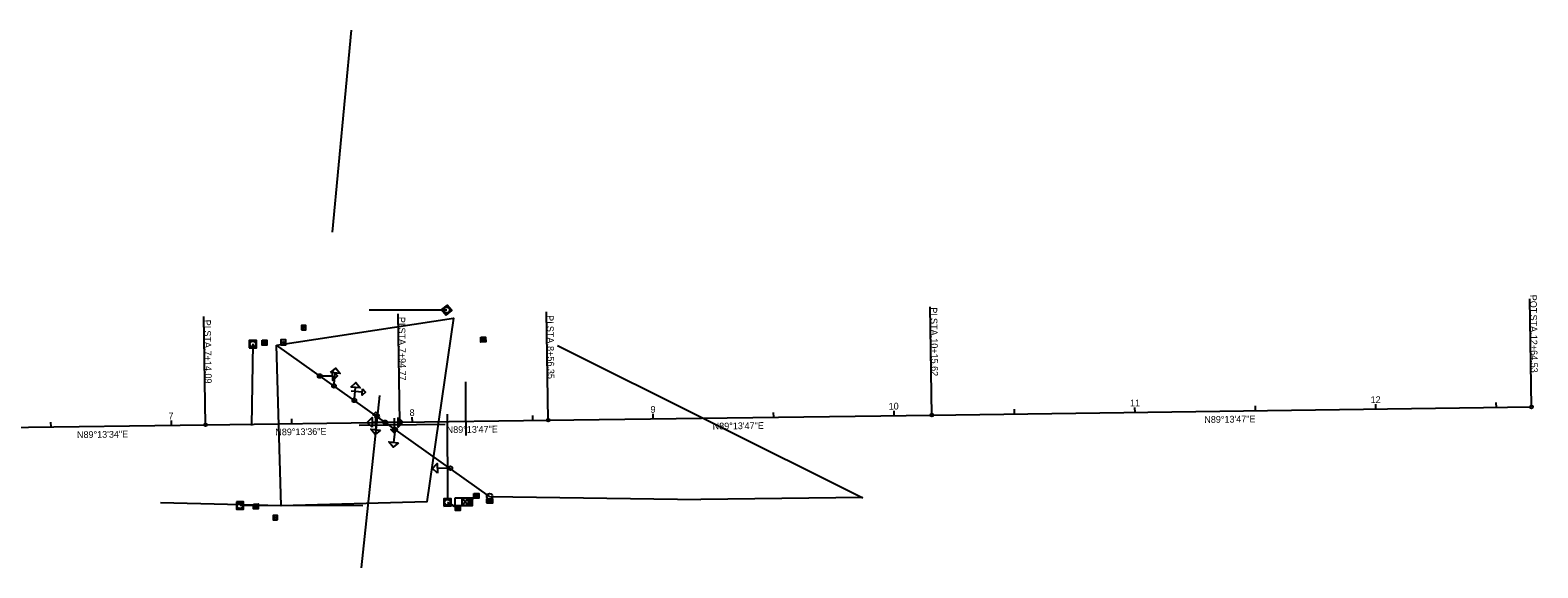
# Model space of a CAD drawing. Extents: x 1369241 to 1370511, y 405823 to 406278.
# Drawn here: x 1369885 to 1370511, y 405850 to 406073 of the extents above; entities that cross this region are included whole.
import ezdxf

# ---------------------------------------------------------------- set-up
doc = ezdxf.new("R2010")
doc.units = 0
for name, color, linetype in [('_CIVIL_CONSTRUCTION', 7, 'Continuous'), ('CM_Corridor_Conceptual', 7, 'Continuous'), ('GE_P_Alignment', 7, 'Continuous'), ('MD_P_ACB_B', 7, 'Continuous'), ('MD_P_ACIC_B', 7, 'Continuous'), ('MD_P_CSS_B', 7, 'Continuous'), ('MD_P_CURB_FACE_BOT', 7, 'Continuous'), ('MD_P_CURB_FACE_TOP', 7, 'Continuous'), ('PF_X_Ground_Line', 7, 'Continuous'), ('PM_P_Crosswalk', 7, 'Continuous'), ('PV_P_Curb', 7, 'Continuous'), ('SC_Scratch1', 7, 'Continuous')]:
    doc.layers.add(name, color=color, linetype=linetype)

msp = doc.modelspace()

# ---------------------------------------------------------------- linework, layer by layer
at = {"layer": '_CIVIL_CONSTRUCTION'}
for p, q in [((1370064.71, 405879.01), (1370067.4, 405876.02)), ((1370067.38, 405879.02), (1370064.73, 405876.01)), ((1370067.38, 405878.33), (1370068.64, 405876.72)), ((1370068.63, 405878.34), (1370067.39, 405876.71)), ((1370074.93, 405878.57), (1370077.43, 405877.07)), ((1370074.93, 405877.07), (1370077.43, 405878.57))]:
    msp.add_line(p, q, dxfattribs=at)
for points in [[(1370061.71, 405878.99), (1370061.73, 405875.99), (1370069.11, 405876.03), (1370069.09, 405879.03)], [(1370061.71, 405878.99), (1370061.73, 405875.99), (1370064.73, 405876.01), (1370064.71, 405879.01)], [(1370064.71, 405879.01), (1370067.38, 405879.02), (1370067.4, 405876.02), (1370064.73, 405876.01)], [(1370067.38, 405878.33), (1370068.63, 405878.34), (1370068.64, 405876.72), (1370067.39, 405876.71)]]:
    msp.add_lwpolyline(points, close=True, dxfattribs=at)
msp.add_lwpolyline([(1370074.93, 405877.07), (1370077.43, 405877.07), (1370077.43, 405878.57), (1370074.93, 405878.57), (1370074.93, 405877.07)], dxfattribs=at)
at = {"layer": 'CM_Corridor_Conceptual'}
for p, q in [((1370006.43, 405929.81), (1370011.03, 405929.86)), ((1370011.63, 405926.51), (1370012.09, 405931.09)), ((1370018.64, 405923.59), (1370023.32, 405923.18)), ((1370020.09, 405920.47), (1370020.49, 405925.05)), ((1370031.96, 405910.55), (1370027.36, 405910.5)), ((1370029.38, 405912.1), (1370028.83, 405907.53)), ((1370028.99, 405908.8), (1370028.94, 405913.5)), ((1370033.56, 405910.56), (1370038.16, 405910.56)), ((1370036.55, 405912.28), (1370036.55, 405907.58)), ((1370036.86, 405906.79), (1370036.31, 405902.22)), ((1370059.06, 405891.48), (1370054.46, 405891.43))]:
    msp.add_line(p, q, dxfattribs=at)
for points in [[(1370010.1, 405931.28), (1370012.29, 405933.08), (1370014.08, 405930.89)], [(1370011.01, 405931.86), (1370013.03, 405929.88), (1370011.05, 405927.86)], [(1370018.49, 405925.21), (1370020.65, 405927.03), (1370022.47, 405924.87)], [(1370023.42, 405924.49), (1370024.64, 405923.05), (1370023.2, 405921.83)], [(1370027.63, 405913.48), (1370028.95, 405914.83), (1370030.3, 405913.51)], [(1370027.39, 405908.5), (1370025.37, 405910.48), (1370027.35, 405912.5)], [(1370030.82, 405907.3), (1370028.59, 405905.55), (1370026.85, 405907.77)], [(1370038.15, 405912.57), (1370040.15, 405910.57), (1370038.15, 405908.57)], [(1370038.3, 405901.99), (1370036.07, 405900.24), (1370034.33, 405902.47)], [(1370037.86, 405907.58), (1370036.52, 405906.25), (1370035.19, 405907.58)], [(1370054.49, 405889.44), (1370052.46, 405891.41), (1370054.44, 405893.44)]]:
    msp.add_lwpolyline(points, close=True, dxfattribs=at)
for centre in [(1370005.63, 405929.8), (1370011.55, 405925.72), (1370020.02, 405919.67), (1370029.48, 405912.89), (1370032.76, 405910.56), (1370032.76, 405910.56), (1370036.96, 405907.58), (1370059.86, 405891.49)]:
    msp.add_circle(centre, 0.8, dxfattribs=at)
at = {"layer": 'GE_P_Alignment'}
for points in [[(1370058.13, 405955.06), (1370060.48, 405956.93), (1370058.61, 405959.27), (1370056.26, 405957.41)], [(1369998.09, 405948.9), (1369999.89, 405948.92), (1369999.87, 405950.72), (1369998.07, 405950.7)], [(1369976.36, 405941.54), (1369979.36, 405941.54), (1369979.36, 405944.54), (1369976.36, 405944.54)], [(1369989.53, 405942.78), (1369991.53, 405942.79), (1369991.53, 405944.79), (1369989.53, 405944.78)], [(1369971.04, 405877.47), (1369971.06, 405874.47), (1369974.06, 405874.49), (1369974.04, 405877.49)], [(1370057.18, 405875.78), (1370060.18, 405875.8), (1370060.15, 405878.8), (1370057.15, 405878.78)], [(1369988.15, 405870.06), (1369988.16, 405871.86), (1369986.36, 405871.87), (1369986.35, 405870.07)]]:
    msp.add_lwpolyline(points, close=True, dxfattribs=at)
for centre, radius in [((1370058.37, 405957.17), 1.2), ((1369998.98, 405949.81), 0.3), ((1369977.86, 405943.04), 1.2), ((1369972.55, 405875.98), 1.2), ((1370058.66, 405877.29), 1.2), ((1370076.17, 405879.77), 1.2), ((1369987.26, 405870.97), 0.3)]:
    msp.add_circle(centre, radius, dxfattribs=at)
msp.add_ellipse((1369990.53, 405943.78), major_axis=(-0.001, 0.333), ratio=0.99991, dxfattribs=at)
at = {"layer": 'MD_P_ACB_B'}
for p, q in [((1369982.71, 405943.63), (1369982.71, 405943.63)), ((1370073.52, 405944.92), (1370073.52, 405944.92)), ((1370070.66, 405879.99), (1370070.66, 405879.99)), ((1369979.14, 405875.63), (1369979.14, 405875.63)), ((1370062.97, 405874.89), (1370062.97, 405874.89))]:
    msp.add_line(p, q, dxfattribs=at)
for points in [[(1370072.51, 405945.91), (1370074.51, 405945.93), (1370074.53, 405943.93), (1370072.53, 405943.91)], [(1369981.69, 405944.61), (1369983.69, 405944.64), (1369983.72, 405942.64), (1369981.72, 405942.61)], [(1369978.12, 405876.61), (1369980.12, 405876.64), (1369980.15, 405874.64), (1369978.15, 405874.61)], [(1370069.65, 405880.98), (1370071.65, 405880.99), (1370071.66, 405879), (1370069.67, 405878.98)], [(1370061.97, 405875.89), (1370063.97, 405875.9), (1370063.98, 405873.9), (1370061.98, 405873.89)]]:
    msp.add_lwpolyline(points, close=True, dxfattribs=at)
for points in [[(1370072.61, 405945.57), (1370073.44, 405945.58)], [(1370073.03, 405945.58), (1370073.05, 405944.25)], [(1370073.6, 405944.25), (1370073.59, 405945.59), (1370074.09, 405945.59), (1370074.14, 405945.58), (1370074.22, 405945.56), (1370074.25, 405945.54), (1370074.28, 405945.52), (1370074.32, 405945.47), (1370074.36, 405945.42), (1370074.38, 405945.33), (1370074.38, 405945.21), (1370074.37, 405945.17), (1370074.35, 405945.1), (1370074.31, 405945.03), (1370074.27, 405945), (1370074.23, 405944.97), (1370074.21, 405944.96), (1370074.18, 405944.95), (1370074.09, 405944.94), (1370073.6, 405944.94)], [(1369981.8, 405944.28), (1369982.62, 405944.29)], [(1369982.22, 405944.29), (1369982.23, 405942.95)], [(1369982.79, 405942.96), (1369982.77, 405944.29), (1369983.28, 405944.3), (1369983.33, 405944.29), (1369983.4, 405944.27), (1369983.44, 405944.25), (1369983.47, 405944.23), (1369983.51, 405944.18), (1369983.54, 405944.13), (1369983.56, 405944.04), (1369983.57, 405943.92), (1369983.56, 405943.87), (1369983.54, 405943.81), (1369983.49, 405943.74), (1369983.45, 405943.71), (1369983.42, 405943.68), (1369983.4, 405943.67), (1369983.37, 405943.66), (1369983.28, 405943.65), (1369982.78, 405943.64)], [(1369983.28, 405943.65), (1369983.58, 405942.97)], [(1370074.09, 405944.94), (1370074.39, 405944.26)], [(1370069.75, 405880.65), (1370070.58, 405880.66)], [(1370070.17, 405880.65), (1370070.18, 405879.32)], [(1370070.74, 405879.32), (1370070.73, 405880.66), (1370071.23, 405880.66), (1370071.29, 405880.65), (1370071.36, 405880.63), (1370071.39, 405880.61), (1370071.42, 405880.59), (1370071.47, 405880.53), (1370071.5, 405880.48), (1370071.52, 405880.4), (1370071.52, 405880.27), (1370071.51, 405880.23), (1370071.49, 405880.17), (1370071.45, 405880.09), (1370071.4, 405880.06), (1370071.37, 405880.04), (1370071.35, 405880.03), (1370071.32, 405880.02), (1370071.23, 405880.01), (1370070.73, 405880.01)], [(1370071.23, 405880.01), (1370071.52, 405879.33)], [(1369978.22, 405876.28), (1369979.05, 405876.29)], [(1369978.64, 405876.29), (1369978.66, 405874.95)], [(1369979.22, 405874.96), (1369979.2, 405876.29), (1369979.7, 405876.3), (1369979.76, 405876.29), (1369979.83, 405876.27), (1369979.86, 405876.25), (1369979.89, 405876.23), (1369979.94, 405876.18), (1369979.97, 405876.13), (1369979.99, 405876.04), (1369979.99, 405875.92), (1369979.98, 405875.88), (1369979.96, 405875.81), (1369979.92, 405875.74), (1369979.88, 405875.71), (1369979.85, 405875.68), (1369979.83, 405875.67), (1369979.8, 405875.66), (1369979.7, 405875.65), (1369979.21, 405875.64)], [(1369979.7, 405875.65), (1369980.01, 405874.97)], [(1370062.06, 405875.56), (1370062.89, 405875.56)], [(1370062.48, 405875.56), (1370062.49, 405874.22)], [(1370063.05, 405874.23), (1370063.04, 405875.56), (1370063.55, 405875.56), (1370063.6, 405875.55), (1370063.67, 405875.53), (1370063.7, 405875.51), (1370063.74, 405875.49), (1370063.78, 405875.44), (1370063.81, 405875.39), (1370063.83, 405875.3), (1370063.83, 405875.18), (1370063.82, 405875.14), (1370063.8, 405875.07), (1370063.76, 405875), (1370063.72, 405874.97), (1370063.69, 405874.95), (1370063.67, 405874.93), (1370063.63, 405874.92), (1370063.54, 405874.91), (1370063.05, 405874.91)], [(1370063.54, 405874.91), (1370063.84, 405874.23)]]:
    msp.add_lwpolyline(points, dxfattribs=at)
at = {"layer": 'MD_P_ACIC_B'}
for p, q in [((1370058.66, 405877.29), (1370062.97, 405874.89)), ((1370062.97, 405874.89), (1370058.72, 405877.29))]:
    msp.add_line(p, q, dxfattribs=at)
at = {"layer": 'MD_P_CSS_B'}
for p, q in [((1370144.09, 405912.02), (1370144.06, 405914.02)), ((1370194.08, 405912.69), (1370194.05, 405914.69)), ((1370244.08, 405913.36), (1370244.05, 405915.36)), ((1370259.7, 405913.57), (1370508.58, 405916.92)), ((1370294.07, 405914.03), (1370294.05, 405916.03)), ((1370344.07, 405914.7), (1370344.04, 405916.7)), ((1370394.06, 405915.38), (1370394.04, 405917.38)), ((1370444.06, 405916.05), (1370444.03, 405918.05)), ((1370494.05, 405916.72), (1370494.03, 405918.72)), ((1369874.22, 405908.38), (1369958.19, 405909.51)), ((1369894.11, 405908.65), (1369894.08, 405910.65)), ((1369944.1, 405909.32), (1369944.08, 405911.32)), ((1369958.19, 405909.51), (1370038.86, 405910.6)), ((1369994.1, 405910), (1369994.07, 405912)), ((1370038.86, 405910.6), (1370100.44, 405911.43)), ((1370044.09, 405910.67), (1370044.07, 405912.67)), ((1370094.09, 405911.34), (1370094.06, 405913.34)), ((1370100.44, 405911.43), (1370259.7, 405913.57))]:
    msp.add_line(p, q, dxfattribs=at)
at = {"layer": 'MD_P_CURB_FACE_BOT'}
msp.add_line((1370104.3, 405942.47), (1370231.02, 405879.25), dxfattribs=at)
at = {"layer": 'MD_P_CURB_FACE_TOP'}
for q in [(1369987.68, 405942.54), (1370163.86, 405878.56)]:
    msp.add_line((1370076.17, 405879.77), q, dxfattribs=at)
at = {"layer": 'PF_X_Ground_Line'}
msp.add_lwpolyline([(1369987.68, 405942.54), (1370061.12, 405953.86), (1370050.05, 405877.5), (1369989.67, 405875.86)], close=True, dxfattribs=at)
at = {"layer": 'PM_P_Crosswalk'}
for p, q in [((1370259.7, 405913.57), (1370259.09, 405958.57)), ((1370508.58, 405916.92), (1370507.97, 405961.91)), ((1369958.19, 405909.51), (1369957.59, 405954.51)), ((1370038.86, 405910.6), (1370038.26, 405955.6)), ((1370100.44, 405911.43), (1370099.84, 405956.43)), ((1370066.09, 405927.4), (1370066.2, 405916.85)), ((1370022.95, 405850.1), (1370030.55, 405921.68)), ((1370066.2, 405916.85), (1370066.31, 405905.12)), ((1370057.75, 405909.6), (1370022.08, 405909.21)), ((1369989.67, 405875.86), (1369939.59, 405877.13)), ((1370231.04, 405879.34), (1370163.86, 405878.56))]:
    msp.add_line(p, q, dxfattribs=at)
for centre in [(1370259.7, 405913.57), (1370508.58, 405916.92), (1369958.19, 405909.51), (1370038.86, 405910.6), (1370100.44, 405911.43)]:
    msp.add_circle(centre, 0.6, dxfattribs=at)
at = {"layer": 'PV_P_Curb'}
msp.add_line((1370010.95, 405989.49), (1370018.81, 406073.44), dxfattribs=at)
at = {"layer": 'SC_Scratch1'}
for p, q in [((1370058.37, 405957.17), (1370026.14, 405957.19)), ((1369977.88, 405943.12), (1369977.28, 405909.21)), ((1370058.54, 405913.96), (1370058.65, 405878.61)), ((1369972.67, 405876.08), (1370023.5, 405876.02))]:
    msp.add_line(p, q, dxfattribs=at)

# ---------------------------------------------------------------- texts
at = {"layer": 'MD_P_CSS_B'}
for s, rotation, p in [('12', 0.77029, (1370441.86, 405918.52)), ('7', 0.77388, (1369942.89, 405911.81)), ('8', 0.77029, (1370042.96, 405913.16)), ('9', 0.77029, (1370142.97, 405914.5)), ('10', 0.77029, (1370241.81, 405915.83)), ('11', 0.77029, (1370342, 405917.18))]:
    msp.add_text(s, height=2.8, rotation=rotation, dxfattribs=at).set_placement(p)
at = {"layer": 'PM_P_Crosswalk'}
for s, rotation, p in [('PI', 270.77029, (1370259.14, 405958.28)), ('POT', 270.77029, (1370507.99, 405963.52)), ('PI', 270.7732, (1369957.65, 405953.14)), ('PI', 270.77029, (1370038.32, 405954.33)), ('PI', 270.77029, (1370099.9, 405955.04)), (' STA. ', 270.77029, (1370259.19, 405954.89)), (' STA. ', 270.77029, (1370508.09, 405956.32)), (' STA. ', 270.7732, (1369957.69, 405949.75)), (' STA. ', 270.77029, (1370038.36, 405950.94)), (' STA. ', 270.77029, (1370099.94, 405951.65)), ('12+64.53', 270.77029, (1370508.22, 405946.87)), ('7+14.09', 270.7732, (1369957.82, 405940.3)), ('7+94.77', 270.77029, (1370038.49, 405941.49)), ('8+56.35', 270.77029, (1370100.07, 405942.2)), ('10+15.62', 270.77029, (1370259.31, 405945.43)), ('N89°13\'36"E', 0.7732, (1369987.23, 405905.1)), ('N89°13\'47"E', 0.77029, (1370058.35, 405906.06)), ('N89°13\'47"E', 0.77029, (1370168.77, 405907.55)), ('N89°13\'47"E', 0.77029, (1370372.84, 405910.29)), ('N89°13\'34"E', 0.77388, (1369904.91, 405903.99))]:
    msp.add_text(s, height=2.8, rotation=rotation, dxfattribs=at).set_placement(p)

doc.saveas('drawing.dxf')
